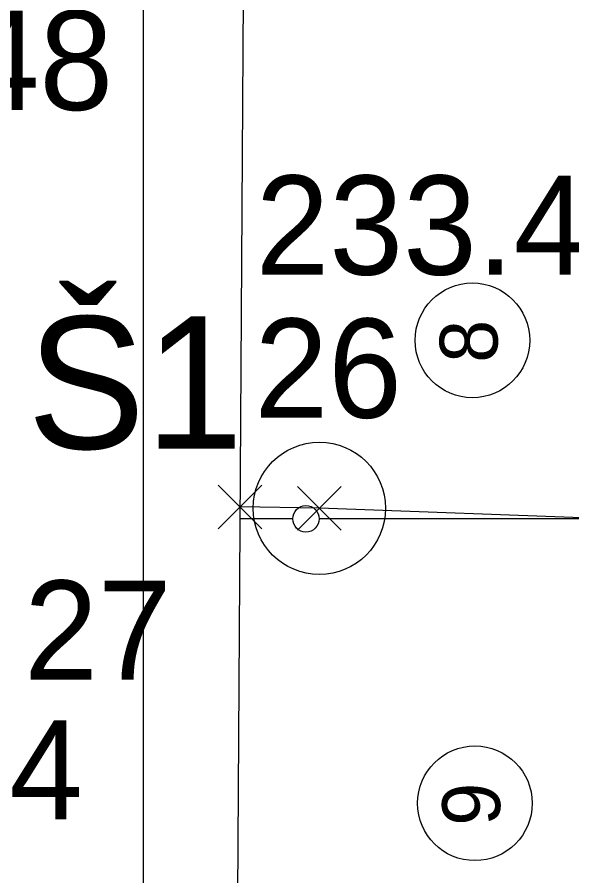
# Model space of a CAD drawing. Extents: x -264031 to -263588, y -1242281 to -1242059.
# Drawn here: x -263926.05 to -263917.66, y -1242133.98 to -1242121 of the extents above; entities that cross this region are included whole.
import ezdxf

# ---------------------------------------------------------------- set-up
doc = ezdxf.new("R2010")
doc.units = 0
for name, color, linetype in [('HESCON_OSI_STAVBY_KFA', 7, 'Continuous'), ('KFA_2D_SITUACIA_DSP', 7, 'Continuous'), ('KFA_BODY_CISLO', 7, 'Continuous'), ('KFA_BODY_SYMBOL', 7, 'Continuous'), ('KFA_BODY_VYSKA', 7, 'Continuous'), ('KFA_JESTV_IS_DSP_-_KANAL_SPLASK', 7, 'Continuous'), ('KFA_SO-40-1-II_SK_MER_TRIBUNA_A', 7, 'Continuous'), ('POPIS', 7, 'Continuous')]:
    doc.layers.add(name, color=color, linetype=linetype)

msp = doc.modelspace()

# ---------------------------------------------------------------- linework, layer by layer
at = {"layer": 'HESCON_OSI_STAVBY_KFA'}
for centre in [(-263919.163, -1242125.883), (-263919.125, -1242132.883)]:
    msp.add_circle(centre, 0.867, dxfattribs=at)
at = {"layer": 'KFA_2D_SITUACIA_DSP'}
for p, q in [((-263924.143, -1242082.64), (-263924.143, -1242185.14)), ((-263921.881, -1242128.582), (-263922.681, -1242128.582)), ((-263917.093, -1242128.582), (-263921.481, -1242128.582))]:
    msp.add_line(p, q, dxfattribs=at)
msp.add_circle((-263921.681, -1242128.582), 0.2, dxfattribs=at)
at = {"layer": 'KFA_BODY_SYMBOL'}
for p, q in [((-263923.012, -1242128.735), (-263922.349, -1242128.072)), ((-263922.349, -1242128.735), (-263923.012, -1242128.072)), ((-263921.81, -1242128.755), (-263921.147, -1242128.092)), ((-263921.147, -1242128.755), (-263921.81, -1242128.092))]:
    msp.add_line(p, q, dxfattribs=at)
at = {"layer": 'KFA_JESTV_IS_DSP_-_KANAL_SPLASK'}
msp.add_line((-263922.558, -1242109.317), (-263922.76, -1242140.975), dxfattribs=at)
at = {"layer": 'KFA_SO-40-1-II_SK_MER_TRIBUNA_A'}
msp.add_lwpolyline([(-263917.093, -1242128.582), (-263921.478, -1242128.423), (-263922.68, -1242128.403)], dxfattribs=at)
msp.add_circle((-263921.478, -1242128.423), 1, dxfattribs=at)

# ---------------------------------------------------------------- texts
at = {"layer": 'HESCON_OSI_STAVBY_KFA'}
for s, p in [('8', (-263918.782, -1242126.223)), ('9', (-263918.744, -1242133.223))]:
    msp.add_text(s, height=0.875, rotation=90, dxfattribs=at).set_placement(p)
at = {"layer": 'KFA_BODY_CISLO'}
for s, p in [('26', (-263922.46, -1242127.054)), ('27', (-263925.945, -1242131.015))]:
    msp.add_text(s, height=1.5, dxfattribs=at).set_placement(p)
at = {"layer": 'KFA_BODY_VYSKA'}
for s, p in [('233.48', (-263930.734, -1242122.4)), ('233.45', (-263922.443, -1242124.891)), ('233.44', (-263931.19, -1242133.128))]:
    msp.add_text(s, height=1.5, dxfattribs=at).set_placement(p)
at = {"layer": 'POPIS'}
msp.add_text('Š1', height=2, dxfattribs=at).set_placement((-263925.899, -1242127.522))

doc.saveas('drawing.dxf')
